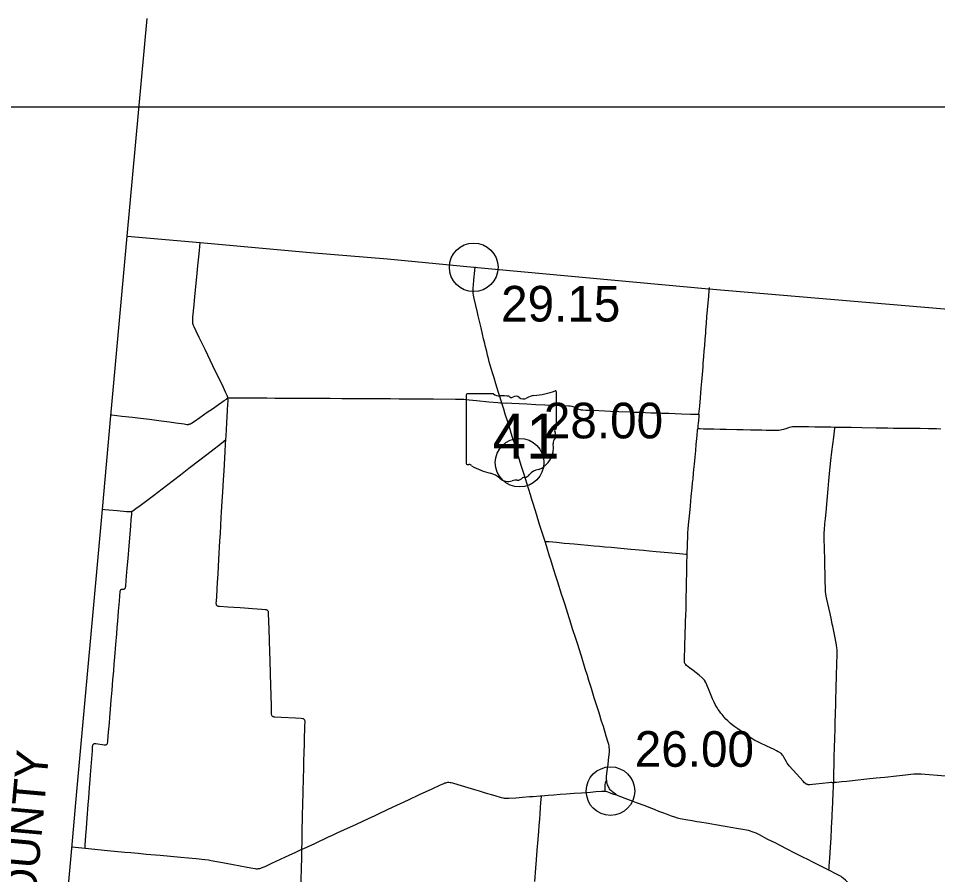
# Model space of a CAD drawing. Extents: x 1597222 to 1925846, y 496284 to 911751.
# Drawn here: x 1640665 to 1669044, y 607664 to 634099 of the extents above; entities that cross this region are included whole.
import ezdxf

# ---------------------------------------------------------------- set-up
doc = ezdxf.new("R2010")
doc.units = 0
for name, color, linetype in [('Default', 7, 'Continuous'), ('GM_X_Adjacent_County', 7, 'Continuous'), ('GM_X_Adjacent_County_Text', 7, 'Continuous'), ('GM_X_County', 7, 'Continuous'), ('GM_X_County_Road', 7, 'Continuous'), ('GM_X_State_Route', 7, 'Continuous'), ('GM_X_State_Shield', 7, 'Continuous'), ('GM_X_Township_Road', 7, 'Continuous'), ('SC_Scratch1', 7, 'Continuous')]:
    doc.layers.add(name, color=color, linetype=linetype)

msp = doc.modelspace()

# ---------------------------------------------------------------- linework, layer by layer
at = {"layer": 'Default'}
for centre in [(1654722, 626414), (1654722, 626414), (1654722, 626414), (1656138, 620383), (1656138, 620383), (1658944, 610243), (1658944, 610243)]:
    msp.add_circle(centre, 750, dxfattribs=at)
at = {"layer": 'GM_X_Adjacent_County'}
msp.add_line((1644023, 627376), (1644636, 634099), dxfattribs=at)
at = {"layer": 'GM_X_County'}
msp.add_lwpolyline([(1641954, 604485), (1642314, 608472), (1642473, 610227), (1643260, 618938), (1643522, 621830), (1644023, 627376), (1646278, 627176), (1649675, 626876), (1652057, 626672), (1654722, 626423), (1661976, 625747), (1675318, 624618), (1678685, 624323), (1679159, 624282), (1682349, 624003), (1686356, 623652), (1687189, 623580), (1693117, 623083), (1698190, 622658)], dxfattribs=at)
at = {"layer": 'GM_X_County_Road'}
for points in [[(1647134, 622373), (1647133, 622383), (1647129, 622397), (1647120, 622429), (1647108, 622460), (1647061, 622564), (1646963, 622771), (1646856, 622993), (1646670, 623376), (1646429, 623879), (1646251, 624248), (1646158, 624440), (1646094, 624573), (1646073, 624618), (1646062, 624649), (1646053, 624681), (1646048, 624714), (1646046, 624747), (1646047, 624797), (1646053, 624879), (1646091, 625254), (1646116, 625515), (1646173, 626119), (1646206, 626461), (1646233, 626739), (1646252, 626935), (1646276, 627178)], [(1647069, 621093), (1647075, 621204), (1647099, 621613), (1647121, 621989), (1647135, 622201), (1647138, 622283), (1647138, 622321), (1647136, 622353), (1647134, 622373)], [(1647134, 622373), (1647162, 622382), (1647177, 622385), (1647192, 622387), (1647339, 622387), (1647667, 622385), (1647929, 622383), (1648339, 622379), (1648585, 622377), (1649044, 622375), (1649322, 622374), (1649847, 622372), (1650289, 622370), (1650650, 622367), (1651010, 622366), (1651273, 622364), (1651551, 622362), (1651699, 622362), (1651830, 622361), (1651977, 622360), (1652158, 622359), (1652420, 622357), (1652862, 622355), (1653043, 622353), (1653174, 622353), (1653485, 622351), (1654157, 622348), (1654304, 622344), (1654419, 622338), (1654582, 622323), (1654810, 622301), (1655185, 622262), (1655462, 622235), (1655544, 622228), (1655590, 622224)], [(1655590, 622224), (1655720, 622226), (1655900, 622216), (1656130, 622207), (1656359, 622196), (1656638, 622183), (1656917, 622170), (1657162, 622157), (1657490, 622144), (1657654, 622137), (1657703, 622133), (1657752, 622125), (1657784, 622117), (1657830, 622101), (1657874, 622079), (1657932, 622049), (1657962, 622035), (1657993, 622024), (1658009, 622020), (1658041, 622014), (1658090, 622009), (1658188, 622005), (1658319, 621999), (1658582, 621989), (1658942, 621975), (1659205, 621963), (1659582, 621947), (1659680, 621944), (1659828, 621939), (1660024, 621933), (1660188, 621926), (1660352, 621919), (1660516, 621913), (1660680, 621908), (1660745, 621906), (1660942, 621899), (1661139, 621893), (1661417, 621885), (1661565, 621881), (1661677, 621876)], [(1661677, 621876), (1661676, 621829), (1661674, 621796), (1661663, 621696), (1661662, 621680), (1661652, 621596), (1661646, 621530), (1661644, 621497), (1661643, 621479), (1661640, 621441)], [(1661640, 621441), (1661680, 621438), (1661714, 621436), (1661811, 621431), (1661942, 621427), (1662040, 621424), (1662139, 621422), (1662335, 621418), (1662516, 621414), (1662844, 621406), (1663041, 621402), (1663270, 621397), (1663500, 621394), (1663615, 621392), (1663746, 621389), (1663845, 621387), (1664008, 621382), (1664091, 621383), (1664140, 621386), (1664188, 621392), (1664236, 621402), (1664300, 621420), (1664394, 621449), (1664472, 621475), (1664519, 621487), (1664568, 621496), (1664617, 621500), (1664682, 621502), (1664797, 621501), (1664961, 621499), (1665060, 621496), (1665256, 621491), (1665502, 621487), (1665749, 621484), (1665874, 621483)], [(1665874, 621483), (1665945, 621482), (1666126, 621479), (1666372, 621475), (1666700, 621470), (1667143, 621462), (1667389, 621458), (1667504, 621456), (1667684, 621452), (1667898, 621451), (1668505, 621443), (1668767, 621440), (1668931, 621437), (1669013, 621434), (1669144, 621423)], [(1649417, 608447), (1649423, 608665), (1649428, 608961), (1649439, 609485), (1649456, 610191), (1649468, 610666), (1649474, 610912), (1649479, 611142), (1649488, 611453), (1649493, 611667), (1649501, 611912), (1649508, 612142), (1649512, 612273), (1649515, 612371), (1649514, 612404), (1649512, 612419), (1649508, 612434), (1649501, 612448), (1649490, 612458), (1649477, 612466), (1649463, 612472), (1649447, 612475), (1649399, 612481), (1649219, 612491), (1648777, 612518), (1648580, 612529), (1648563, 612530), (1648546, 612533), (1648530, 612538), (1648515, 612547), (1648502, 612559), (1648493, 612573), (1648487, 612589), (1648484, 612606), (1648482, 612639), (1648478, 612886), (1648469, 613181), (1648449, 613853), (1648435, 614296), (1648429, 614509), (1648413, 614919), (1648394, 615509), (1648389, 615706), (1648388, 615738), (1648385, 615771), (1648382, 615786), (1648376, 615801), (1648368, 615813), (1648357, 615823), (1648344, 615830), (1648329, 615835), (1648314, 615837), (1648281, 615840), (1648182, 615846), (1647888, 615869), (1647643, 615888), (1647512, 615898), (1647316, 615912), (1647136, 615925), (1646873, 615940), (1646857, 615941), (1646840, 615944), (1646824, 615948), (1646808, 615956), (1646795, 615968), (1646786, 615982), (1646780, 615998), (1646777, 616015), (1646776, 616032), (1646787, 616229), (1646803, 616491), (1646814, 616688), (1646830, 616950), (1646855, 617392), (1646888, 617965), (1646901, 618195), (1646915, 618440), (1646928, 618686), (1646938, 618850), (1646958, 619194), (1646975, 619472), (1646998, 619848), (1647014, 620127), (1647036, 620520), (1647047, 620716), (1647061, 620962), (1647069, 621093)], [(1649417, 608447), (1649473, 608473), (1649816, 608630), (1650263, 608838), (1650337, 608872), (1650509, 608952), (1650717, 609049), (1651105, 609226), (1651492, 609406), (1651655, 609482), (1651804, 609551), (1652043, 609661), (1652236, 609752), (1652458, 609857), (1652711, 609976), (1653053, 610135), (1653440, 610315), (1653692, 610435), (1653797, 610481), (1653828, 610493), (1653859, 610503), (1653892, 610510), (1653925, 610514), (1653958, 610515), (1653991, 610513), (1654024, 610508), (1654072, 610497), (1654230, 610451), (1654748, 610293), (1654890, 610250), (1655078, 610193), (1655377, 610103), (1655565, 610048), (1655629, 610032), (1655661, 610025), (1655693, 610022), (1655741, 610021), (1655807, 610023), (1656019, 610040), (1656232, 610056), (1656445, 610072), (1656559, 610081), (1656772, 610096), (1656818, 610100)], [(1658775, 610242), (1658776, 610282), (1658776, 610314), (1658778, 610363), (1658783, 610429), (1658794, 610510), (1658797, 610528), (1658801, 610541), (1658808, 610554), (1658815, 610563), (1658827, 610571)], [(1656818, 610100), (1657017, 610114), (1657197, 610128), (1657394, 610144), (1657574, 610158), (1657819, 610176), (1658048, 610193), (1658326, 610214), (1658490, 610227), (1658670, 610240), (1658735, 610244), (1658769, 610243), (1658775, 610242)], [(1658775, 610242), (1658785, 610241), (1658802, 610238), (1658834, 610229), (1658880, 610211), (1659002, 610162), (1659033, 610150), (1659057, 610143), (1659090, 610137), (1659117, 610134)], [(1656608, 607454), (1656641, 607863), (1656660, 608125), (1656683, 608419), (1656710, 608746), (1656732, 609007), (1656744, 609171), (1656760, 609383), (1656771, 609530), (1656788, 609743), (1656808, 610004), (1656813, 610053), (1656818, 610100)], [(1642323, 608518), (1642417, 608507), (1642725, 608478)], [(1642725, 608478), (1642825, 608469), (1643119, 608441), (1643413, 608414), (1643952, 608362), (1644132, 608345), (1644361, 608323), (1644606, 608300), (1645047, 608260), (1645358, 608233), (1645684, 608202), (1646158, 608157), (1646419, 608130), (1646534, 608117), (1646615, 608104), (1646970, 608037), (1647292, 607976), (1647728, 607895), (1647905, 607862), (1647970, 607852), (1648002, 607848), (1648035, 607847), (1648051, 607847), (1648083, 607850), (1648114, 607856), (1648146, 607865), (1648192, 607882), (1648282, 607920), (1648491, 608016), (1649027, 608265), (1649235, 608362), (1649417, 608447)], [(1649322, 603954), (1649326, 604008), (1649329, 604106), (1649333, 604319), (1649337, 604648), (1649344, 605205), (1649350, 605550), (1649359, 605943), (1649377, 606747), (1649382, 606944), (1649394, 607518), (1649403, 607846), (1649412, 608206), (1649417, 608436), (1649417, 608447)]]:
    msp.add_lwpolyline(points, dxfattribs=at)
at = {"layer": 'GM_X_State_Route'}
for points in [[(1665919, 607682), (1665689, 607800), (1665443, 607922), (1665195, 608049), (1665033, 608129), (1664901, 608195), (1664798, 608246), (1664637, 608328), (1664403, 608447), (1664185, 608560), (1664024, 608641), (1663804, 608752), (1663542, 608888), (1663439, 608939), (1663379, 608966), (1663319, 608990), (1663272, 609006), (1663209, 609023), (1663145, 609037), (1663032, 609057), (1662838, 609089), (1662725, 609109), (1662482, 609151), (1662191, 609201), (1661965, 609242), (1661706, 609284), (1661609, 609299), (1661463, 609322), (1661269, 609352), (1661155, 609373), (1661091, 609387), (1661012, 609408), (1660933, 609433), (1660825, 609472), (1660672, 609530), (1660564, 609571), (1660442, 609618), (1660304, 609672), (1660136, 609736), (1660013, 609784), (1659752, 609882), (1659645, 609922), (1659399, 610014), (1659261, 610067), (1659185, 610099), (1659141, 610121), (1659117, 610134), (1659098, 610146), (1659057, 610174), (1659018, 610205), (1658982, 610238), (1658958, 610262), (1658937, 610287), (1658918, 610314), (1658900, 610342), (1658884, 610371), (1658869, 610401), (1658857, 610432), (1658843, 610479), (1658835, 610511), (1658829, 610544), (1658827, 610571), (1658825, 610593), (1658823, 610643), (1658825, 610709), (1658830, 610774), (1658842, 610872), (1658868, 611067), (1658883, 611198), (1658904, 611377), (1658909, 611442), (1658911, 611491), (1658911, 611540), (1658907, 611589), (1658901, 611637), (1658891, 611685), (1658874, 611748), (1658816, 611936), (1658724, 612234), (1658670, 612406), (1658591, 612657), (1658543, 612813), (1658513, 612907), (1658445, 613127), (1658358, 613409), (1658329, 613503), (1658280, 613659), (1658230, 613815), (1658166, 614019), (1658045, 614411), (1657967, 614661), (1657942, 614739), (1657880, 614926), (1657775, 615255), (1657720, 615426), (1657625, 615724), (1657541, 615990), (1657492, 616146), (1657436, 616318), (1657317, 616693), (1657248, 616912), (1657199, 617069), (1657155, 617209), (1657100, 617382), (1657066, 617491), (1656987, 617742), (1656934, 617914), (1656923, 617946), (1656855, 618164), (1656795, 618352), (1656756, 618477), (1656658, 618790), (1656566, 619088), (1656518, 619245), (1656474, 619386), (1656373, 619715), (1656320, 619888), (1656280, 620013), (1656191, 620294), (1656008, 620890), (1655959, 621047), (1655924, 621156), (1655879, 621296), (1655845, 621406), (1655815, 621500), (1655772, 621641), (1655698, 621876), (1655649, 622032), (1655590, 622224), (1655538, 622393), (1655490, 622550), (1655409, 622816), (1655351, 623005), (1655311, 623130), (1655263, 623287), (1655230, 623397), (1655203, 623491), (1655174, 623603), (1655151, 623698), (1655124, 623810), (1655078, 624001), (1655063, 624065), (1655029, 624209), (1654995, 624353), (1654950, 624544), (1654920, 624672), (1654864, 624911), (1654839, 625023), (1654789, 625231), (1654737, 625455), (1654718, 625551), (1654708, 625616), (1654704, 625666), (1654703, 625715), (1654705, 625781), (1654712, 625863), (1654728, 626026), (1654758, 626320), (1654769, 626431)], [(1666356, 607332), (1666324, 607364), (1666198, 607491), (1666139, 607547), (1666102, 607578), (1666062, 607605), (1666020, 607630), (1665919, 607682)]]:
    msp.add_lwpolyline(points, dxfattribs=at)
at = {"layer": 'GM_X_State_Shield'}
for p, q in [((1654490, 622473), (1654490, 620359)), ((1655332, 622509), (1654517, 622509)), ((1657274, 621456), (1657274, 622561)), ((1657274, 621456), (1657274, 621456))]:
    msp.add_line(p, q, dxfattribs=at)
for centre, radius, start, end in [((1654522, 622477), 32.3, 98.1301, 188.1301), ((1655527, 622754), 313, 231.6195, 271.1119), ((1655630, 621323), 1123, 80.4867, 94.9883), ((1655885, 622488), 90.3, 219.7921, 297.1024), ((1656018, 622244), 188, 54.4667, 119.1411), ((1656260, 622579), 226, 233.8562, 294.8282), ((1656659, 621863), 594, 97.3462, 120.7689), ((1656282, 625390), 2953, 275.8445, 288.9065), ((1657243, 622566), 31, 351.8621, 97.738), ((1657267, 621375), 48, 107.944, 210.337), ((1656962, 621235), 288, 340.033, 23.6496), ((1657241, 621452), 33.2, 289.6038, 7.7341), ((1656448, 620853), 739, 292.3089, 8.9858), ((1657385, 620993), 210, 136.8065, 186.9296), ((1654522, 620355), 32.5, 171.9584, 258.3066), ((1654527, 620571), 248, 267.339, 280.6039), ((1654578, 620237), 89.5, 29.7484, 93.2717), ((1655708, 622136), 2132, 240.4129, 257.1985), ((1656759, 619766), 404, 94.4031, 142.5768), ((1655072, 619410), 667, 47.1842, 75.836), ((1655794, 620227), 423, 230.7004, 286.2918), ((1656039, 619496), 348, 85.6951, 111.2099), ((1656070, 620069), 226, 268.777, 315.5493), ((1656274, 619864), 63.5, 65.7517, 132.6484), ((1656246, 620154), 239, 282.8732, 323.2771)]:
    msp.add_arc(centre, radius, start, end, dxfattribs=at)
at = {"layer": 'GM_X_Township_Road'}
for points in [[(1661677, 621876), (1661700, 622124), (1661721, 622386), (1661745, 622680), (1661763, 622892), (1661782, 623104), (1661792, 623218), (1661803, 623349), (1661810, 623447), (1661828, 623659), (1661841, 623822), (1661854, 624002), (1661869, 624198), (1661883, 624378), (1661891, 624476), (1661908, 624688), (1661924, 624884), (1661942, 625096), (1661979, 625520), (1661994, 625700), (1662000, 625793)], [(1643529, 621862), (1643552, 621859), (1643862, 621822), (1644189, 621783), (1644433, 621756), (1644711, 621721), (1645069, 621675), (1645330, 621640), (1645525, 621616), (1645786, 621579), (1645867, 621566), (1645883, 621565), (1645900, 621564), (1645916, 621565), (1645932, 621568), (1645948, 621572), (1645963, 621578), (1645978, 621585), (1646006, 621602), (1646088, 621657), (1646263, 621779), (1646494, 621937), (1646656, 622048), (1646844, 622181), (1647019, 622304), (1647085, 622348), (1647104, 622359), (1647134, 622373)], [(1661311, 617560), (1661312, 617641), (1661317, 617756), (1661324, 617904), (1661328, 618067), (1661330, 618133), (1661335, 618231), (1661343, 618329), (1661355, 618459), (1661390, 618835), (1661410, 619047), (1661438, 619341), (1661465, 619602), (1661481, 619765), (1661492, 619879), (1661510, 620059), (1661522, 620173), (1661537, 620336), (1661557, 620548), (1661577, 620761), (1661594, 620940), (1661603, 621038), (1661619, 621218), (1661635, 621391), (1661640, 621441)], [(1665837, 610518), (1665839, 610543), (1665841, 610593), (1665844, 610790), (1665849, 611085), (1665854, 611347), (1665859, 611544), (1665870, 611905), (1665878, 612134), (1665885, 612397), (1665890, 612593), (1665893, 612692), (1665898, 612872), (1665904, 613069), (1665912, 613397), (1665925, 613823), (1665942, 614479), (1665941, 614561), (1665939, 614610), (1665933, 614659), (1665917, 614756), (1665856, 615078), (1665807, 615336), (1665793, 615400), (1665765, 615528), (1665724, 615721), (1665686, 615897), (1665627, 616170), (1665607, 616266), (1665593, 616347), (1665587, 616396), (1665581, 616478), (1665571, 616756), (1665567, 616953), (1665561, 617183), (1665557, 617363), (1665548, 617757), (1665543, 618019), (1665542, 618134), (1665544, 618216), (1665550, 618314), (1665566, 618494), (1665581, 618657), (1665599, 618853), (1665644, 619343), (1665665, 619572), (1665688, 619817), (1665710, 620045), (1665749, 620454), (1665778, 620715), (1665835, 621170), (1665869, 621447), (1665874, 621483)], [(1644166, 618882), (1644170, 618883), (1644186, 618890), (1644200, 618898), (1644294, 618965), (1644426, 619063), (1644834, 619367), (1645237, 619676), (1645665, 620008), (1645770, 620087), (1645926, 620208), (1646263, 620468), (1646614, 620739), (1646939, 620989), (1647069, 621093)], [(1643264, 618942), (1643335, 618936), (1643711, 618906), (1644005, 618880), (1644087, 618874), (1644121, 618874), (1644137, 618875), (1644154, 618878), (1644166, 618882)], [(1642725, 608478), (1642727, 608507), (1642730, 608573), (1642750, 608867), (1642768, 609097), (1642790, 609408), (1642821, 609817), (1642837, 610030), (1642863, 610357), (1642881, 610586), (1642894, 610750), (1642913, 610995), (1642949, 611486), (1642957, 611618), (1642960, 611651), (1642964, 611667), (1642970, 611681), (1642979, 611694), (1642992, 611703), (1643007, 611708), (1643023, 611710), (1643056, 611708), (1643318, 611674), (1643351, 611672), (1643367, 611674), (1643382, 611679), (1643396, 611686), (1643407, 611697), (1643415, 611711), (1643421, 611727), (1643426, 611760), (1643441, 611956), (1643475, 612349), (1643488, 612512), (1643509, 612774), (1643532, 613052), (1643557, 613363), (1643584, 613674), (1643607, 613952), (1643624, 614165), (1643641, 614377), (1643673, 614770), (1643701, 615097), (1643718, 615293), (1643733, 615490), (1643760, 615800), (1643788, 616111), (1643801, 616274), (1643807, 616390), (1643812, 616423), (1643816, 616438), (1643823, 616452), (1643833, 616464), (1643847, 616472), (1643863, 616477), (1643879, 616478), (1643913, 616478), (1643929, 616480), (1643944, 616485), (1643957, 616493), (1643966, 616506), (1643973, 616521), (1643977, 616537), (1643981, 616570), (1643996, 616750), (1644025, 617127), (1644050, 617421), (1644083, 617813), (1644133, 618419), (1644152, 618631), (1644164, 618778), (1644168, 618837), (1644167, 618863), (1644166, 618882)], [(1656923, 617946), (1656955, 617947), (1656987, 617947), (1657053, 617944), (1657282, 617923), (1657511, 617902), (1657674, 617888), (1657822, 617875), (1658034, 617856), (1658247, 617837), (1658443, 617819), (1658607, 617805), (1658770, 617788), (1658966, 617770), (1659260, 617743), (1659571, 617715), (1659963, 617678), (1660143, 617662), (1660356, 617642), (1660601, 617619), (1660961, 617588), (1661075, 617577), (1661173, 617569), (1661272, 617562), (1661311, 617560)], [(1665835, 610489), (1665816, 610497), (1665797, 610502), (1665783, 610504), (1665752, 610505), (1665670, 610498), (1665279, 610458), (1665181, 610448), (1665099, 610440), (1665067, 610439), (1665050, 610440), (1665034, 610443), (1665019, 610447), (1665004, 610453), (1664989, 610461), (1664976, 610470), (1664963, 610480), (1664938, 610502), (1664894, 610550), (1664684, 610781), (1664474, 611011), (1664431, 611061), (1664402, 611101), (1664376, 611142), (1664297, 611286), (1664271, 611328), (1664252, 611354), (1664231, 611379), (1664219, 611391), (1664194, 611412), (1664168, 611431), (1664126, 611458), (1664069, 611490), (1663996, 611526), (1663773, 611630), (1663550, 611734), (1663476, 611770), (1663405, 611810), (1663307, 611870), (1663114, 611995), (1663005, 612068), (1662871, 612162), (1662779, 612231), (1662702, 612292), (1662639, 612344), (1662566, 612410), (1662508, 612468), (1662452, 612528), (1662388, 612603), (1662347, 612654), (1662308, 612707), (1662271, 612761), (1662229, 612831), (1662181, 612917), (1662144, 612990), (1662096, 613095), (1662030, 613244), (1661966, 613395), (1661885, 613593), (1661871, 613623), (1661864, 613637), (1661846, 613665), (1661836, 613678), (1661815, 613702), (1661779, 613736), (1661678, 613820), (1661499, 613964), (1661343, 614084), (1661291, 614124), (1661267, 614147), (1661256, 614159), (1661247, 614172), (1661239, 614186), (1661233, 614201), (1661229, 614217), (1661226, 614233), (1661225, 614249), (1661225, 614282), (1661231, 614413), (1661238, 614610), (1661242, 614790), (1661248, 615003), (1661249, 615069), (1661253, 615183), (1661257, 615298), (1661263, 615462), (1661271, 615691), (1661276, 615839), (1661279, 615953), (1661281, 616035), (1661282, 616117), (1661284, 616281), (1661287, 616429), (1661290, 616593), (1661294, 616789), (1661297, 616888), (1661301, 617051), (1661306, 617297), (1661310, 617510), (1661311, 617560)], [(1665837, 610518), (1665863, 610518), (1665880, 610518), (1665927, 610522), (1666090, 610538), (1666236, 610553), (1666498, 610580), (1666857, 610617), (1667151, 610649), (1667412, 610677), (1667771, 610716), (1668049, 610747), (1668212, 610765), (1668310, 610774), (1668375, 610777), (1668440, 610776), (1668539, 610772), (1669292, 610719)], [(1665689, 607800), (1665692, 607875), (1665694, 607924), (1665711, 608170), (1665737, 608513), (1665756, 608791), (1665772, 609102), (1665781, 609299), (1665787, 609430), (1665792, 609545), (1665797, 609660), (1665823, 610184), (1665831, 610380), (1665832, 610446), (1665834, 610462), (1665834, 610477), (1665835, 610489)], [(1665835, 610489), (1665837, 610518)]]:
    msp.add_lwpolyline(points, dxfattribs=at)
at = {"layer": 'SC_Scratch1'}
msp.add_lwpolyline([(1597222, 631367), (1793472, 631367), (1793472, 496867), (1597222, 496867)], close=True, dxfattribs=at)

# ---------------------------------------------------------------- texts
at = {"layer": 'Default'}
for s, p in [('29.15', (1655567, 624740)), ('29.15', (1655567, 624740)), ('28.00', (1656888, 621133)), ('28.00', (1656888, 621133)), ('26.00', (1659694, 610993)), ('26.00', (1659694, 610993))]:
    msp.add_text(s, height=1100, dxfattribs=at).set_placement(p)
at = {"layer": 'GM_X_Adjacent_County_Text'}
msp.add_text('GREENE COUNTY', height=1000, rotation=84.8167, dxfattribs=at).set_placement((1640562, 599835))
at = {"layer": 'GM_X_State_Shield'}
msp.add_text('41', height=1392.2, dxfattribs=at).set_placement((1655304, 620508))

doc.saveas('drawing.dxf')
